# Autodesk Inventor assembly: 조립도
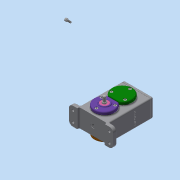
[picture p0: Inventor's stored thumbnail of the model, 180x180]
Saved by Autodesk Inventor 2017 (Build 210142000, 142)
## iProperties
Part Number: 조립도
Material: 일반
Document SubType Name: Assembly
Designer: 222
Author: 222
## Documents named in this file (24)
- C:\Users\222\Desktop\600506V1029\조립도.iam
- C:\Users\222\Desktop\600506V1029\본체.ipt
- C:\Users\222\Desktop\600506V1029\Ű 4 x 4 x 12.ipt
- C:\Users\222\Desktop\600506V1029\Ű 5 x 5 x 12.ipt
- C:\Users\222\Desktop\600506V1029\개스킷 A.ipt
- C:\Users\222\Desktop\600506V1029\개스킷 B.ipt
- C:\Users\222\Desktop\600506V1029\개스킷 C.ipt
- C:\Users\222\Desktop\600506V1029\베어링 6001.ipt
- 베어링 6001.ipt
- C:\Users\222\Desktop\600506V1029\베어링 6002.ipt
- 베어링 6002.ipt
- C:\Users\222\Desktop\600506V1029\볼트 M4.ipt
- C:\Users\222\Desktop\600506V1029\스퍼기어 A.ipt
- C:\Users\222\Desktop\600506V1029\스퍼기어 B.ipt
- C:\Users\222\Desktop\600506V1029\오일 실 10 20 7.ipt
- C:\Users\222\Desktop\600506V1029\오일 실 12 22 7.ipt
- C:\Users\222\Desktop\600506V1029\축 A.ipt
- C:\Users\222\Desktop\600506V1029\축 B.ipt
- C:\Users\222\Desktop\600506V1029\칼라.ipt
- C:\Users\222\Desktop\600506V1029\커버 A.ipt
- C:\Users\222\Desktop\600506V1029\커버 B.ipt
- C:\Users\222\Desktop\600506V1029\커버 C.ipt
- C:\Users\222\Desktop\600506V1029\커버 D.ipt
- C:\Users\222\Desktop\600506V1029\커버 E.ipt
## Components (7 placed, 5 different names)
1. Ű 4 x 4 x 12:1
2. Ű 5 x 5 x 12:1
3. 개스킷 A:1
4. 개스킷 B:1
5. 개스킷 C:1
6. 개스킷 B:2
7. 개스킷 B:3
